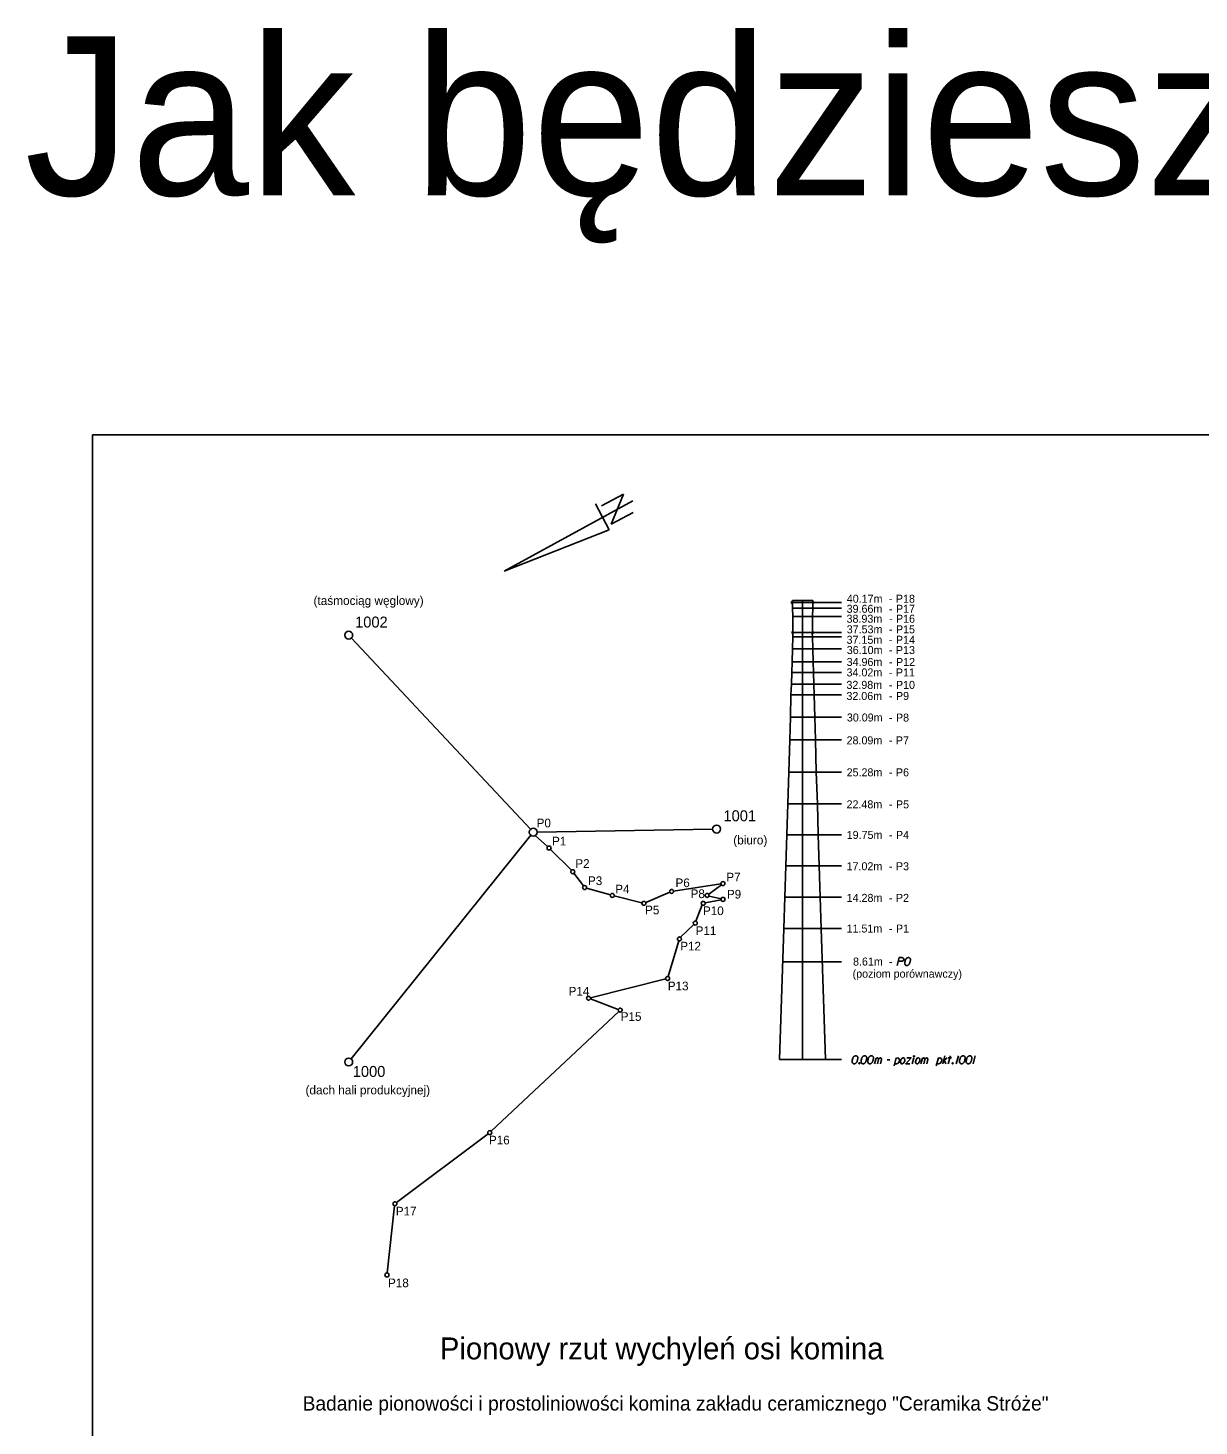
# Model space of a CAD drawing. Extents: x 138 to 264, y -75 to 121.
# Drawn here: x 137.57 to 167.2, y 85.26 to 120.63 of the extents above; entities that cross this region are included whole.
import ezdxf

# ---------------------------------------------------------------- set-up
doc = ezdxf.new("R2010")
doc.units = 0
for name, color, linetype in [('15 listopad 2008', 7, 'Continuous'), ('Default', 7, 'Continuous'), ('Opisy', 7, 'Continuous'), ('Standart wykresów', 7, 'Continuous'), ('Wykresy 4 maj 2008', 7, 'Continuous')]:
    doc.layers.add(name, color=color, linetype=linetype)

msp = doc.modelspace()

# ---------------------------------------------------------------- linework, layer by layer
at = {"layer": '15 listopad 2008'}
msp.add_lwpolyline([(139.203, 110.337), (257.14, 110.337), (257.14, 47.785), (139.203, 47.785)], close=True, dxfattribs=at)
at = {"layer": 'Opisy'}
for p, q in [((156.89, 106.121), (156.89, 106.097)), ((156.912, 106.121), (156.89, 106.121)), ((157.169, 106.097), (156.89, 106.097)), ((156.89, 106.097), (156.89, 106.072)), ((156.912, 106.145), (156.912, 106.121)), ((156.912, 106.145), (157.21, 106.145)), ((157.169, 94.531), (157.169, 106.145)), ((157.169, 106.097), (158.158, 106.097)), ((157.427, 106.145), (157.21, 106.145)), ((157.427, 106.145), (157.427, 106.121)), ((157.427, 106.121), (157.449, 106.121)), ((157.449, 106.121), (157.449, 106.097)), ((157.449, 106.097), (157.449, 106.072)), ((156.912, 106.072), (156.89, 106.072)), ((156.912, 105.949), (156.912, 106.072)), ((157.169, 105.949), (156.912, 105.949)), ((156.92, 105.739), (156.912, 105.949)), ((157.169, 105.949), (158.158, 105.949)), ((157.418, 105.739), (157.427, 105.949)), ((157.427, 106.072), (157.449, 106.072)), ((157.427, 105.949), (157.427, 106.072)), ((157.169, 105.739), (156.92, 105.739)), ((156.92, 105.739), (156.92, 105.361)), ((157.169, 105.739), (158.158, 105.739)), ((157.418, 105.739), (157.418, 105.361)), ((156.903, 105.361), (156.903, 105.335)), ((156.903, 105.361), (156.92, 105.361)), ((157.169, 105.335), (156.903, 105.335)), ((156.903, 105.335), (156.903, 105.31)), ((156.923, 105.31), (156.903, 105.31)), ((156.912, 104.923), (156.92, 105.227)), ((156.92, 105.227), (156.923, 105.31)), ((157.169, 105.227), (156.92, 105.227)), ((157.169, 105.335), (158.158, 105.335)), ((157.169, 105.227), (158.158, 105.227)), ((157.418, 105.227), (157.416, 105.31)), ((157.416, 105.31), (157.436, 105.31)), ((157.436, 105.361), (157.418, 105.361)), ((157.427, 104.923), (157.418, 105.227)), ((157.436, 105.361), (157.436, 105.335)), ((157.436, 105.335), (157.436, 105.31)), ((156.903, 104.594), (156.912, 104.923)), ((157.169, 104.923), (156.912, 104.923)), ((157.169, 104.923), (158.158, 104.923)), ((157.436, 104.594), (157.427, 104.923)), ((156.895, 104.324), (156.903, 104.594)), ((157.169, 104.594), (156.903, 104.594)), ((157.169, 104.594), (158.158, 104.594)), ((157.444, 104.324), (157.436, 104.594)), ((156.877, 103.759), (156.887, 104.025)), ((156.887, 104.025), (156.895, 104.324)), ((157.169, 104.025), (156.887, 104.025)), ((157.169, 104.324), (156.895, 104.324)), ((157.169, 104.324), (158.158, 104.324)), ((157.169, 104.025), (158.158, 104.025)), ((157.452, 104.025), (157.444, 104.324)), ((157.462, 103.759), (157.452, 104.025)), ((156.861, 103.192), (156.877, 103.759)), ((157.169, 103.759), (156.877, 103.759)), ((157.169, 103.759), (158.158, 103.759)), ((157.477, 103.192), (157.462, 103.759)), ((156.844, 102.618), (156.861, 103.192)), ((157.169, 103.192), (156.861, 103.192)), ((157.169, 103.192), (158.158, 103.192)), ((157.495, 102.618), (157.477, 103.192)), ((156.821, 101.807), (156.844, 102.618)), ((157.169, 102.618), (156.844, 102.618)), ((157.169, 102.618), (158.158, 102.618)), ((157.518, 101.807), (157.495, 102.618)), ((156.795, 101.003), (156.821, 101.807)), ((157.169, 101.807), (156.821, 101.807)), ((157.169, 101.807), (158.158, 101.807)), ((157.544, 101.003), (157.518, 101.807)), ((156.771, 100.217), (156.795, 101.003)), ((157.169, 101.003), (156.795, 101.003)), ((157.169, 101.003), (158.158, 101.003)), ((157.568, 100.217), (157.544, 101.003)), ((156.746, 99.432), (156.771, 100.217)), ((157.169, 100.217), (156.771, 100.217)), ((157.169, 100.217), (158.158, 100.217)), ((157.593, 99.432), (157.568, 100.217)), ((156.722, 98.641), (156.746, 99.432)), ((157.169, 99.432), (156.746, 99.432)), ((157.169, 99.432), (158.158, 99.432)), ((157.617, 98.641), (157.593, 99.432)), ((156.696, 97.845), (156.722, 98.641)), ((157.169, 98.641), (156.722, 98.641)), ((157.169, 98.641), (158.158, 98.641)), ((157.643, 97.845), (157.617, 98.641)), ((156.587, 94.531), (156.696, 97.845)), ((157.169, 97.845), (156.696, 97.845)), ((157.169, 97.845), (158.158, 97.845)), ((157.751, 94.531), (157.643, 97.845)), ((157.169, 97.009), (156.669, 97.009)), ((157.169, 97.009), (158.158, 97.009)), ((157.169, 94.531), (156.587, 94.531)), ((157.169, 94.531), (158.158, 94.531))]:
    msp.add_line(p, q, dxfattribs=at)
for points in [[(159.562, 96.911), (159.616, 97.114), (159.685, 97.114), (159.694, 97.112), (159.699, 97.11), (159.708, 97.106), (159.715, 97.101), (159.72, 97.095), (159.724, 97.087), (159.728, 97.075), (159.729, 97.066), (159.728, 97.058), (159.726, 97.052), (159.723, 97.045), (159.72, 97.04), (159.715, 97.034), (159.708, 97.029), (159.704, 97.026), (159.696, 97.023), (159.688, 97.021), (159.592, 97.021)], [(159.852, 97.114), (159.849, 97.114), (159.839, 97.112), (159.833, 97.11), (159.828, 97.109), (159.82, 97.106), (159.81, 97.101), (159.802, 97.096), (159.795, 97.09), (159.79, 97.083), (159.785, 97.075), (159.78, 97.067), (159.775, 97.058), (159.772, 97.052), (159.769, 97.042), (159.764, 97.026), (159.759, 97.002), (159.756, 96.983), (159.756, 96.965), (159.758, 96.953), (159.764, 96.938), (159.769, 96.93), (159.777, 96.921), (159.787, 96.914), (159.791, 96.913), (159.801, 96.911), (159.809, 96.911), (159.822, 96.913), (159.833, 96.916), (159.841, 96.921), (159.852, 96.929), (159.857, 96.934), (159.863, 96.94), (159.868, 96.946), (159.871, 96.951), (159.874, 96.959), (159.876, 96.962), (159.879, 96.97), (159.882, 96.98), (159.885, 96.989), (159.887, 96.996), (159.889, 97.001), (159.89, 97.007), (159.893, 97.021), (159.895, 97.029), (159.897, 97.037), (159.898, 97.048), (159.9, 97.063), (159.9, 97.067), (159.898, 97.074), (159.897, 97.08), (159.892, 97.09), (159.887, 97.096), (159.882, 97.101), (159.876, 97.106), (159.869, 97.109), (159.865, 97.11), (159.86, 97.112), (159.852, 97.114)], [(158.521, 94.629), (158.518, 94.629), (158.508, 94.628), (158.502, 94.626), (158.497, 94.624), (158.489, 94.621), (158.479, 94.616), (158.471, 94.612), (158.463, 94.605), (158.459, 94.599), (158.454, 94.591), (158.449, 94.583), (158.444, 94.573), (158.441, 94.567), (158.438, 94.557), (158.433, 94.541), (158.428, 94.518), (158.425, 94.498), (158.425, 94.481), (158.427, 94.468), (158.433, 94.454), (158.438, 94.446), (158.446, 94.436), (158.455, 94.43), (158.46, 94.428), (158.47, 94.427), (158.478, 94.427), (158.491, 94.428), (158.502, 94.432), (158.51, 94.436), (158.521, 94.444), (158.526, 94.449), (158.532, 94.455), (158.537, 94.462), (158.54, 94.467), (158.543, 94.475), (158.545, 94.478), (158.548, 94.486), (158.551, 94.495), (158.554, 94.505), (158.556, 94.511), (158.557, 94.516), (158.559, 94.522), (158.562, 94.537), (158.564, 94.545), (158.565, 94.553), (158.567, 94.564), (158.569, 94.578), (158.569, 94.583), (158.567, 94.589), (158.565, 94.596), (158.561, 94.605), (158.556, 94.612), (158.551, 94.616), (158.545, 94.621), (158.538, 94.624), (158.534, 94.626), (158.529, 94.628), (158.521, 94.629)], [(158.605, 94.454), (158.613, 94.454), (158.618, 94.451), (158.623, 94.444), (158.623, 94.436), (158.618, 94.43), (158.613, 94.427), (158.605, 94.427), (158.6, 94.43), (158.596, 94.436), (158.596, 94.444), (158.6, 94.451), (158.605, 94.454)], [(158.745, 94.629), (158.742, 94.629), (158.733, 94.628), (158.726, 94.626), (158.722, 94.624), (158.714, 94.621), (158.704, 94.616), (158.696, 94.612), (158.688, 94.605), (158.683, 94.599), (158.679, 94.591), (158.674, 94.583), (158.669, 94.573), (158.666, 94.567), (158.663, 94.557), (158.658, 94.541), (158.653, 94.518), (158.65, 94.498), (158.65, 94.481), (158.651, 94.468), (158.658, 94.454), (158.663, 94.446), (158.671, 94.436), (158.68, 94.43), (158.685, 94.428), (158.694, 94.427), (158.702, 94.427), (158.715, 94.428), (158.726, 94.432), (158.734, 94.436), (158.745, 94.444), (158.75, 94.449), (158.757, 94.455), (158.761, 94.462), (158.765, 94.467), (158.768, 94.475), (158.769, 94.478), (158.773, 94.486), (158.776, 94.495), (158.779, 94.505), (158.781, 94.511), (158.782, 94.516), (158.784, 94.522), (158.787, 94.537), (158.789, 94.545), (158.79, 94.553), (158.792, 94.564), (158.793, 94.578), (158.793, 94.583), (158.792, 94.589), (158.79, 94.596), (158.785, 94.605), (158.781, 94.612), (158.776, 94.616), (158.769, 94.621), (158.763, 94.624), (158.758, 94.626), (158.753, 94.628), (158.745, 94.629)], [(158.916, 94.629), (158.913, 94.629), (158.903, 94.628), (158.897, 94.626), (158.892, 94.624), (158.884, 94.621), (158.875, 94.616), (158.867, 94.612), (158.859, 94.605), (158.854, 94.599), (158.849, 94.591), (158.844, 94.583), (158.839, 94.573), (158.836, 94.567), (158.833, 94.557), (158.828, 94.541), (158.824, 94.518), (158.82, 94.498), (158.82, 94.481), (158.822, 94.468), (158.828, 94.454), (158.833, 94.446), (158.841, 94.436), (158.851, 94.43), (158.855, 94.428), (158.865, 94.427), (158.873, 94.427), (158.886, 94.428), (158.897, 94.432), (158.905, 94.436), (158.916, 94.444), (158.921, 94.449), (158.927, 94.455), (158.932, 94.462), (158.935, 94.467), (158.938, 94.475), (158.94, 94.478), (158.943, 94.486), (158.946, 94.495), (158.949, 94.505), (158.951, 94.511), (158.953, 94.516), (158.954, 94.522), (158.957, 94.537), (158.959, 94.545), (158.961, 94.553), (158.962, 94.564), (158.964, 94.578), (158.964, 94.583), (158.962, 94.589), (158.961, 94.596), (158.956, 94.605), (158.951, 94.612), (158.946, 94.616), (158.94, 94.621), (158.934, 94.624), (158.929, 94.626), (158.924, 94.628), (158.916, 94.629)], [(158.991, 94.427), (159.028, 94.572)], [(159.018, 94.534), (159.026, 94.551), (159.034, 94.561), (159.043, 94.567), (159.053, 94.572), (159.059, 94.575), (159.069, 94.575), (159.072, 94.573), (159.079, 94.567), (159.085, 94.559), (159.09, 94.545), (159.091, 94.537), (159.099, 94.551), (159.109, 94.561), (159.118, 94.567), (159.128, 94.572), (159.136, 94.575), (159.144, 94.575), (159.15, 94.573), (159.155, 94.567), (159.16, 94.559), (159.165, 94.545), (159.166, 94.537), (159.139, 94.427)], [(159.064, 94.427), (159.091, 94.537)], [(159.31, 94.529), (159.378, 94.529)], [(159.487, 94.374), (159.541, 94.573)], [(159.536, 94.556), (159.552, 94.569), (159.576, 94.573), (159.595, 94.57), (159.608, 94.561), (159.617, 94.548), (159.624, 94.53), (159.625, 94.514), (159.622, 94.5), (159.617, 94.483), (159.605, 94.463), (159.589, 94.446), (159.565, 94.43), (159.544, 94.427), (159.525, 94.428), (159.504, 94.44)], [(159.715, 94.573), (159.726, 94.573), (159.738, 94.567), (159.751, 94.549), (159.753, 94.541), (159.754, 94.534), (159.754, 94.527), (159.754, 94.503), (159.75, 94.487), (159.742, 94.468), (159.732, 94.452), (159.716, 94.438), (159.702, 94.427), (159.678, 94.427), (159.668, 94.43), (159.659, 94.438), (159.654, 94.446), (159.648, 94.465), (159.648, 94.494), (159.651, 94.503), (159.657, 94.524), (159.664, 94.535), (159.667, 94.541), (159.683, 94.559), (159.699, 94.569), (159.715, 94.573)], [(159.81, 94.577), (159.914, 94.577), (159.782, 94.427), (159.883, 94.427)], [(159.941, 94.427), (159.982, 94.581)], [(159.985, 94.629), (159.993, 94.629), (159.998, 94.626), (160.003, 94.62), (160.003, 94.612), (159.998, 94.605), (159.993, 94.602), (159.985, 94.602), (159.981, 94.605), (159.976, 94.612), (159.976, 94.62), (159.981, 94.626), (159.985, 94.629)], [(160.097, 94.573), (160.108, 94.573), (160.121, 94.567), (160.134, 94.549), (160.135, 94.541), (160.137, 94.534), (160.137, 94.527), (160.137, 94.503), (160.132, 94.487), (160.124, 94.468), (160.115, 94.452), (160.099, 94.438), (160.084, 94.427), (160.06, 94.427), (160.051, 94.43), (160.041, 94.438), (160.036, 94.446), (160.03, 94.465), (160.03, 94.494), (160.033, 94.503), (160.04, 94.524), (160.046, 94.535), (160.049, 94.541), (160.065, 94.559), (160.081, 94.569), (160.097, 94.573)], [(160.164, 94.427), (160.201, 94.572)], [(160.191, 94.534), (160.199, 94.551), (160.207, 94.561), (160.217, 94.567), (160.226, 94.572), (160.233, 94.575), (160.242, 94.575), (160.245, 94.573), (160.252, 94.567), (160.258, 94.559), (160.263, 94.545), (160.264, 94.537), (160.272, 94.551), (160.282, 94.561), (160.291, 94.567), (160.301, 94.572), (160.309, 94.575), (160.317, 94.575), (160.323, 94.573), (160.328, 94.567), (160.333, 94.559), (160.338, 94.545), (160.339, 94.537), (160.312, 94.427)], [(160.237, 94.427), (160.264, 94.537)], [(160.554, 94.374), (160.609, 94.573)], [(160.604, 94.556), (160.62, 94.569), (160.644, 94.573), (160.663, 94.57), (160.676, 94.561), (160.685, 94.548), (160.691, 94.53), (160.693, 94.514), (160.69, 94.5), (160.685, 94.483), (160.672, 94.463), (160.656, 94.446), (160.633, 94.43), (160.612, 94.427), (160.593, 94.428), (160.572, 94.44)], [(160.715, 94.427), (160.77, 94.629)], [(160.735, 94.498), (160.83, 94.578)], [(160.754, 94.514), (160.795, 94.427)], [(160.857, 94.427), (160.91, 94.629)], [(160.857, 94.573), (160.934, 94.573)], [(160.961, 94.454), (160.969, 94.454), (160.974, 94.451), (160.978, 94.444), (160.978, 94.436), (160.974, 94.43), (160.969, 94.427), (160.961, 94.427), (160.956, 94.43), (160.951, 94.436), (160.951, 94.444), (160.956, 94.451), (160.961, 94.454)], [(161.114, 94.629), (161.06, 94.427)], [(161.236, 94.629), (161.233, 94.629), (161.224, 94.628), (161.217, 94.626), (161.213, 94.624), (161.205, 94.621), (161.195, 94.616), (161.187, 94.612), (161.179, 94.605), (161.174, 94.599), (161.17, 94.591), (161.165, 94.583), (161.16, 94.573), (161.157, 94.567), (161.154, 94.557), (161.149, 94.541), (161.144, 94.518), (161.141, 94.498), (161.141, 94.481), (161.142, 94.468), (161.149, 94.454), (161.154, 94.446), (161.162, 94.436), (161.171, 94.43), (161.176, 94.428), (161.185, 94.427), (161.193, 94.427), (161.206, 94.428), (161.217, 94.432), (161.225, 94.436), (161.236, 94.444), (161.241, 94.449), (161.248, 94.455), (161.252, 94.462), (161.256, 94.467), (161.259, 94.475), (161.26, 94.478), (161.264, 94.486), (161.267, 94.495), (161.27, 94.505), (161.272, 94.511), (161.273, 94.516), (161.275, 94.522), (161.278, 94.537), (161.279, 94.545), (161.281, 94.553), (161.283, 94.564), (161.284, 94.578), (161.284, 94.583), (161.283, 94.589), (161.281, 94.596), (161.276, 94.605), (161.272, 94.612), (161.267, 94.616), (161.26, 94.621), (161.254, 94.624), (161.249, 94.626), (161.244, 94.628), (161.236, 94.629)], [(161.407, 94.629), (161.404, 94.629), (161.394, 94.628), (161.388, 94.626), (161.383, 94.624), (161.375, 94.621), (161.366, 94.616), (161.358, 94.612), (161.35, 94.605), (161.345, 94.599), (161.34, 94.591), (161.335, 94.583), (161.33, 94.573), (161.327, 94.567), (161.324, 94.557), (161.319, 94.541), (161.315, 94.518), (161.311, 94.498), (161.311, 94.481), (161.313, 94.468), (161.319, 94.454), (161.324, 94.446), (161.332, 94.436), (161.342, 94.43), (161.346, 94.428), (161.356, 94.427), (161.364, 94.427), (161.377, 94.428), (161.388, 94.432), (161.396, 94.436), (161.407, 94.444), (161.412, 94.449), (161.418, 94.455), (161.423, 94.462), (161.426, 94.467), (161.429, 94.475), (161.431, 94.478), (161.434, 94.486), (161.437, 94.495), (161.44, 94.505), (161.442, 94.511), (161.444, 94.516), (161.445, 94.522), (161.448, 94.537), (161.45, 94.545), (161.452, 94.553), (161.453, 94.564), (161.455, 94.578), (161.455, 94.583), (161.453, 94.589), (161.452, 94.596), (161.447, 94.605), (161.442, 94.612), (161.437, 94.616), (161.431, 94.621), (161.424, 94.624), (161.42, 94.626), (161.415, 94.628), (161.407, 94.629)], [(161.536, 94.629), (161.482, 94.427)]]:
    msp.add_lwpolyline(points, dxfattribs=at)
at = {"layer": 'Standart wykresów'}
for p, q in [((152.877, 108.666), (149.622, 106.886)), ((152.277, 107.93), (151.929, 108.588)), ((152.638, 108.835), (152.081, 108.538)), ((152.328, 108.075), (152.638, 108.835)), ((152.885, 108.371), (152.328, 108.075)), ((149.622, 106.886), (152.277, 107.93)), ((145.688, 105.269), (145.688, 105.269)), ((150.288, 100.358), (145.757, 105.196)), ((150.293, 100.207), (145.751, 94.549)), ((150.456, 100.287), (154.895, 100.362)), ((154.995, 100.364), (154.995, 100.364)), ((145.688, 94.471), (145.688, 94.471))]:
    msp.add_line(p, q, dxfattribs=at)
for centre in [(145.688, 105.269), (154.995, 100.364), (145.688, 94.471)]:
    msp.add_circle(centre, 0.1, dxfattribs=at)
at = {"layer": 'Wykresy 4 maj 2008'}
for p, q in [((150.407, 100.2), (150.721, 99.921)), ((150.791, 99.85), (151.321, 99.321)), ((151.386, 99.245), (151.626, 98.925)), ((151.704, 98.872), (152.308, 98.699)), ((152.404, 98.673), (153.107, 98.498)), ((153.202, 98.505), (153.81, 98.766)), ((153.905, 98.793), (155.106, 98.978)), ((155.116, 98.955), (154.796, 98.715)), ((154.803, 98.67), (155.107, 98.597)), ((154.63, 98.443), (154.474, 98.032)), ((155.107, 98.576), (154.704, 98.498)), ((154.42, 97.951), (154.086, 97.625)), ((154.043, 97.537), (153.77, 96.633)), ((153.707, 96.573), (151.804, 96.098)), ((151.803, 96.068), (152.509, 95.803)), ((152.519, 95.751), (149.292, 92.72)), ((149.216, 92.655), (146.895, 90.916)), ((146.848, 90.836), (146.661, 89.135))]:
    msp.add_line(p, q, dxfattribs=at)
for centre, radius in [((150.356, 100.285), 0.1), ((150.756, 99.885), 0.05), ((151.356, 99.285), 0.05), ((155.156, 98.985), 0.05), ((151.656, 98.885), 0.05), ((152.356, 98.685), 0.05), ((153.856, 98.785), 0.05), ((154.756, 98.685), 0.05), ((153.156, 98.485), 0.05), ((154.656, 98.485), 0.05), ((155.156, 98.585), 0.05), ((154.456, 97.985), 0.05), ((154.056, 97.585), 0.05), ((153.756, 96.585), 0.05), ((151.756, 96.085), 0.05), ((152.556, 95.785), 0.05), ((149.256, 92.685), 0.05), ((146.856, 90.885), 0.05), ((146.656, 89.085), 0.05)]:
    msp.add_circle(centre, radius, dxfattribs=at)

# ---------------------------------------------------------------- texts
at = {"layer": 'Default'}
msp.add_text('Jak będziesz plotował daj skalę wydruku 0.1', height=4.01714, dxfattribs=at).set_placement((137.489, 116.397))
at = {"layer": 'Opisy'}
for s, height, p in [('40.17m', 0.2024, (158.289, 106.089)), ('-', 0.202, (159.353, 106.089)), ('P18', 0.2024, (159.532, 106.089)), ('38.93m', 0.2024, (158.283, 105.583)), ('39.66m', 0.2024, (158.285, 105.834)), ('-', 0.202, (159.355, 105.834)), ('P17', 0.2024, (159.533, 105.834)), ('P16', 0.2024, (159.533, 105.583)), ('37.53m', 0.2024, (158.287, 105.315)), ('-', 0.202, (159.353, 105.315)), ('-', 0.202, (159.358, 105.583)), ('P15', 0.2024, (159.533, 105.315)), ('37.15m', 0.2024, (158.284, 105.051)), ('-', 0.202, (159.353, 105.051)), ('P14', 0.2024, (159.533, 105.051)), ('34.96m', 0.2024, (158.285, 104.489)), ('36.10m', 0.2024, (158.289, 104.791)), ('-', 0.202, (159.355, 104.791)), ('P13', 0.2024, (159.532, 104.791)), ('P12', 0.2024, (159.534, 104.489)), ('34.02m', 0.2024, (158.283, 104.225)), ('-', 0.202, (159.355, 104.489)), ('P11', 0.2024, (159.532, 104.225)), ('32.98m', 0.2024, (158.28, 103.91)), ('-', 0.202, (159.355, 104.225)), ('-', 0.202, (159.355, 103.91)), ('P10', 0.2024, (159.533, 103.91)), ('32.06m', 0.2024, (158.28, 103.629)), ('-', 0.202, (159.355, 103.629)), ('P9', 0.2024, (159.533, 103.629)), ('30.09m', 0.2024, (158.291, 103.085)), ('P8', 0.2024, (159.533, 103.082)), ('-', 0.202, (159.355, 103.085)), ('28.09m', 0.2024, (158.284, 102.506)), ('-', 0.202, (159.355, 102.506)), ('P7', 0.2024, (159.532, 102.506)), ('25.28m', 0.2024, (158.285, 101.697)), ('P6', 0.2024, (159.532, 101.697)), ('-', 0.202, (159.353, 101.697)), ('22.48m', 0.2024, (158.283, 100.888)), ('-', 0.202, (159.353, 100.888)), ('P5', 0.2024, (159.533, 100.888)), ('19.75m', 0.2024, (158.287, 100.114)), ('-', 0.202, (159.353, 100.114)), ('P4', 0.2024, (159.533, 100.114)), ('17.02m', 0.2024, (158.284, 99.322)), ('-', 0.202, (159.353, 99.322)), ('P3', 0.2024, (159.532, 99.322)), ('14.28m', 0.2024, (158.286, 98.522)), ('P2', 0.2024, (159.532, 98.522)), ('-', 0.202, (159.354, 98.522)), ('11.51m', 0.2024, (158.283, 97.747)), ('-', 0.202, (159.353, 97.747)), ('P1', 0.2024, (159.533, 97.747)), ('8.61m', 0.2024, (158.447, 96.911)), ('-', 0.202, (159.353, 96.911)), ('(poziom porównawczy)', 0.2024, (158.436, 96.604)), ('Pionowy rzut wychyleń osi komina', 0.55314, (147.995, 86.95)), ('Badanie pionowości i prostoliniowości komina zakładu ceramicznego "Ceramika Stróże"', 0.36281, (144.522, 85.655))]:
    msp.add_text(s, height=height, dxfattribs=at).set_placement(p)
at = {"layer": 'Standart wykresów'}
for s, height, p in [('(taśmociąg węglowy)', 0.22315, (144.798, 106.032)), ('1002', 0.2771, (145.85, 105.461)), ('1001', 0.2771, (155.169, 100.561)), ('(biuro)', 0.2231, (155.417, 99.975)), ('1000', 0.2771, (145.791, 94.094)), ('(dach hali produkcyjnej)', 0.22315, (144.595, 93.652))]:
    msp.add_text(s, height=height, dxfattribs=at).set_placement(p)
at = {"layer": 'Wykresy 4 maj 2008'}
for s, p in [('P0', (150.444, 100.407)), ('P1', (150.834, 99.949)), ('P2', (151.422, 99.382)), ('P3', (151.743, 98.947)), ('P6', (153.956, 98.895)), ('P7', (155.242, 99.038)), ('P4', (152.431, 98.736)), ('P8', (154.338, 98.618)), ('P9', (155.256, 98.606)), ('P5', (153.187, 98.207)), ('P10', (154.652, 98.187)), ('P11', (154.466, 97.684)), ('P12', (154.075, 97.292)), ('P14', (151.252, 96.152)), ('P13', (153.761, 96.284)), ('P15', (152.571, 95.512)), ('P16', (149.237, 92.387)), ('P17', (146.88, 90.589)), ('P18', (146.685, 88.774))]:
    msp.add_text(s, height=0.22, dxfattribs=at).set_placement(p)

doc.saveas('drawing.dxf')
